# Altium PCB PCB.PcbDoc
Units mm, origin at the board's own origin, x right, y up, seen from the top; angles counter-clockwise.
Board outline 65.6 x 41.4 mm, 2 copper layers (Top Layer, Bottom Layer), stack 0.533 mm thick; 24 components, 81 nets, 201 pads, 130 vias.
Unrouted connection lines stored in the file: 11.
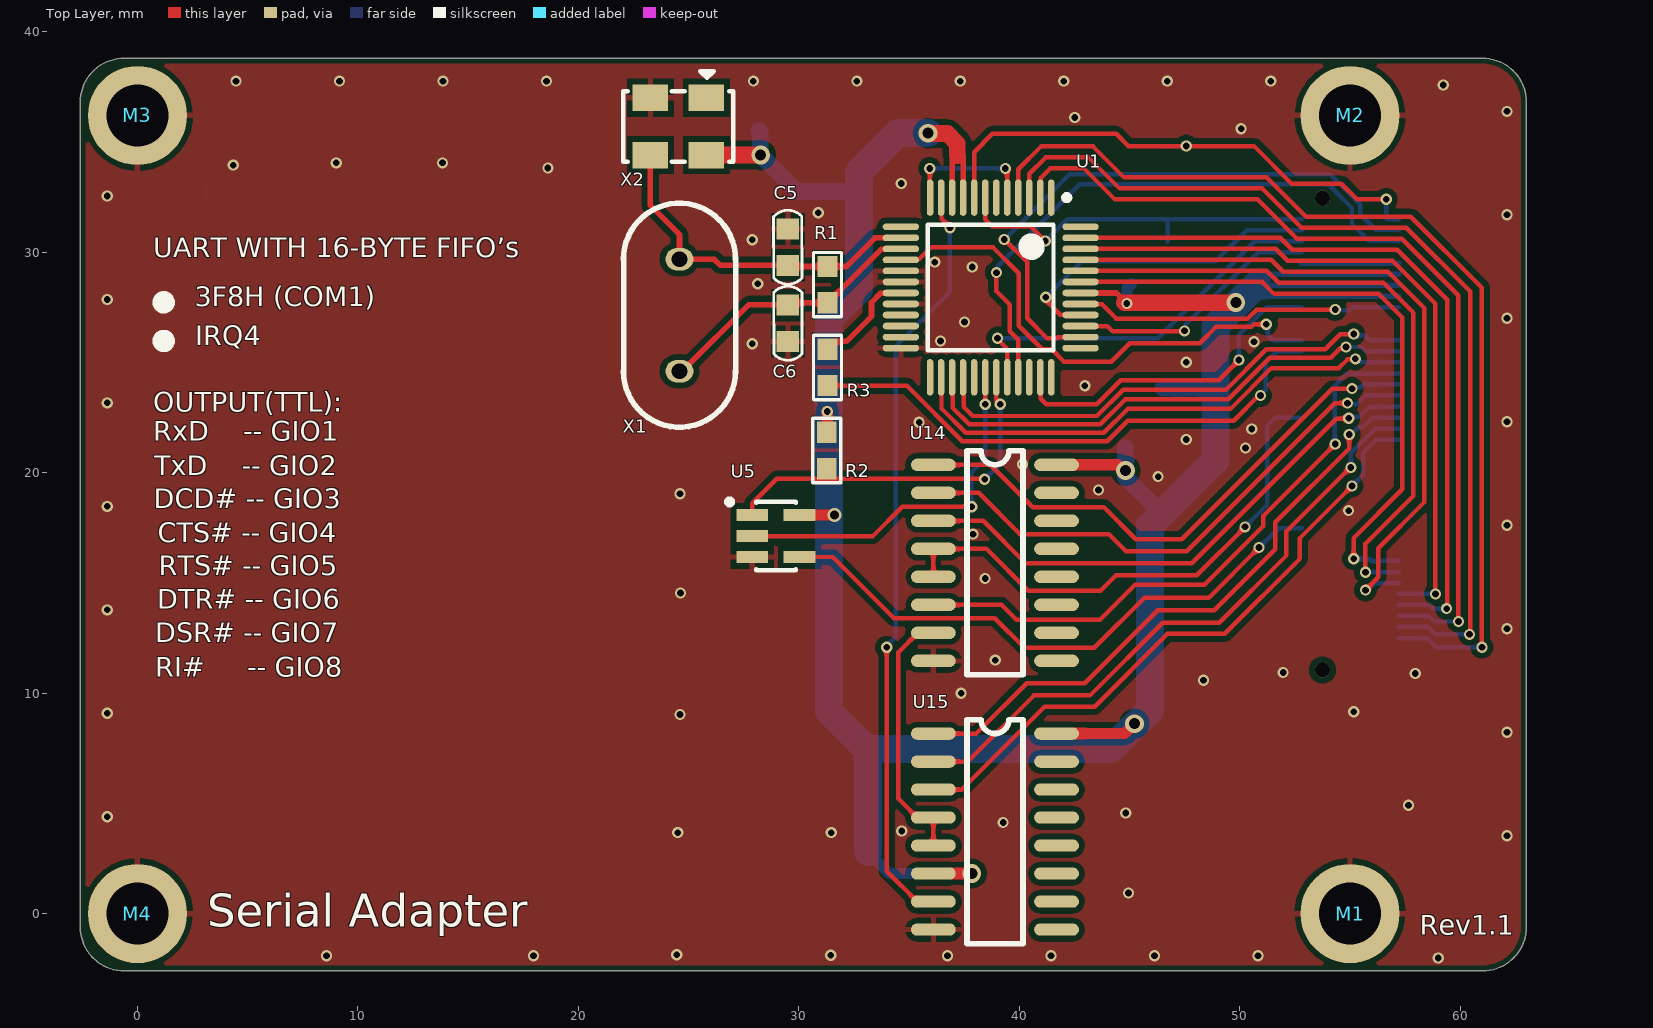
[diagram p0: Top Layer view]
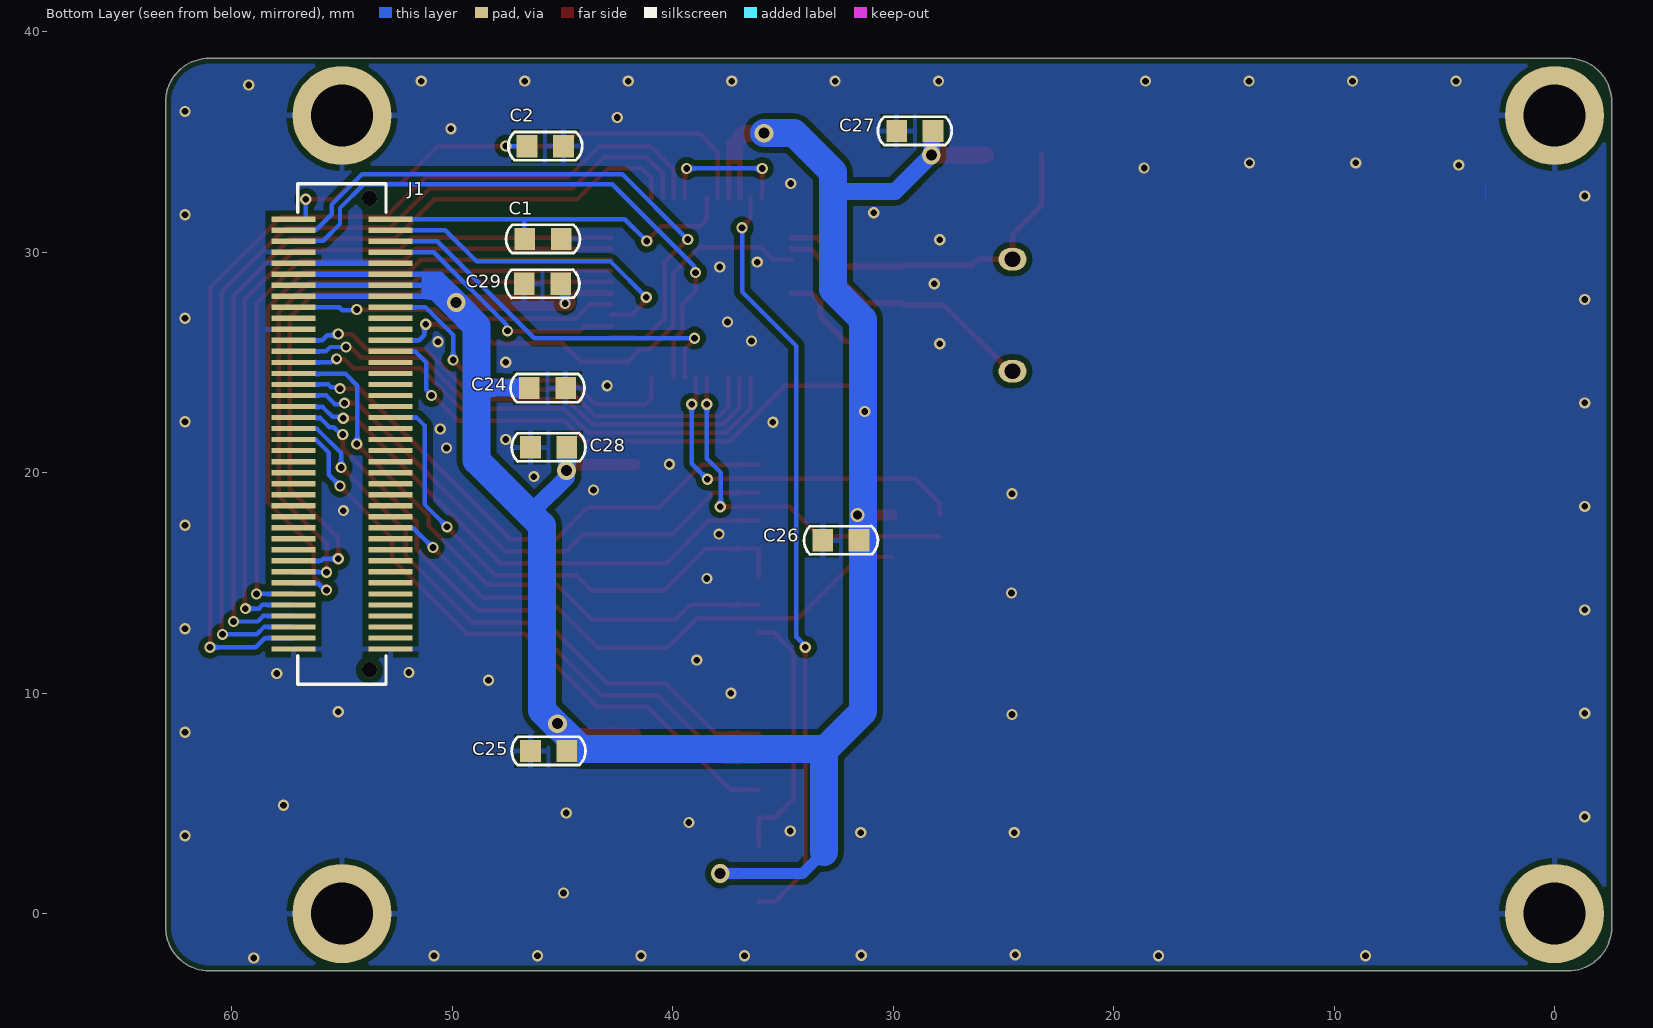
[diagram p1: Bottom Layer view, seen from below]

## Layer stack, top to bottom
Top Solder: solder mask 0.0102, Solder Resist, Dk 3.5
Top Layer: signal copper 0.0356
Dielectric 1: prepreg 0.0711, Composite dielectric, Dk 4.1
Dielectric1: prepreg 0.32, Composite dielectric, Dk 4.1
Dielectric 2: prepreg 0.0711, Composite dielectric, Dk 4.1
Bottom Layer: signal copper 0.0356
Bottom Solder: solder mask 0.0102, Solder Resist, Dk 3.5

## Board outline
-2.6,-0.6 ccw(c-0.6,-0.6) -0.6,-2.6 61,-2.6 ccw(c61,-0.6) 63,-0.6 63,36.803 63,36.8 ccw(c61,36.8) 61,38.8 -0.6,38.8 ccw(c-0.6,36.8) -2.6,36.8

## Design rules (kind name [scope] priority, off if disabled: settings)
BoardOutlineClearance [All] p1: gap=0 ignorepadtopadclearanceinfootprint=FALSE except(0.254: Poly-OutlineEdge Poly-CavityEdge Poly-CutoutEdge Poly-SplitBarrior)
Clearance [All] p1: gap=0.178 ignorepadtopadclearanceinfootprint=FALSE except(0.254: Arc-Fill Arc-Poly Arc-Region Track-Fill Track-Poly Track-Region SMDPad-Fill SMDPad-Poly SMDPad-Region THPad-Fill THPad-Poly THPad-Region Via-Fill Via-Poly Via-Region Fill-Fill Fill-Poly Fill-Region Poly-Poly Poly-Region Region-Region)
ComponentClearance [All] p1: gap=0 collisioncheckmode=3 verticalgap=0 showdistances=FALSE
Height [All] p1: minheight=0 maxheight=254 prefheight=12.7
HoleSize [All] p1: absolutevalues=TRUE maxlimit=254 minlimit=0.025 maxpercent=80.000 minpercent=20.000
MinimumSolderMaskSliver [All] p1: minsoldermaskwidth=0
PlaneClearance [All] p1: clearance=0.381
PlaneConnect PlaneConnect_1 [IsVia] p1: planeconnectstyle=Direct reliefexpansion=0.508 reliefentries=4 reliefconductorwidth=0.254 reliefairgap=0.254
PlaneConnect [All] p2: planeconnectstyle=Relief reliefexpansion=0.508 reliefentries=4 reliefconductorwidth=0.254 reliefairgap=0.254
PolygonConnect PolygonConnect_1 [IsVia] p1: connectstyle=Direct reliefconductorwidth=0.254 reliefentries=4 polygonreliefangle="90 Angle" airgapwidth=0.254
PolygonConnect [All] p2: connectstyle=Relief reliefconductorwidth=0.254 reliefentries=4 polygonreliefangle="90 Angle" airgapwidth=0.254
RoutingVias [All] p1: holewidth=0.305 width=0.559 viastyle="Through Hole" minholewidth=0.305 minwidth=0.508 maxholewidth=1.27 maxwidth=2.54
SilkToSilkClearance [All] p1: silktosilkclearance=0
SilkToSolderMaskClearance [IsPad] p1: minsilkscreentomaskgap=0 clearancetoexposedcopper=TRUE
SolderMaskExpansion [All] p1: expansion=0.102 istentingtop=FALSE useseparateexpansions=TRUE expansionbottom=0.102 istentingbottom=FALSE
UnRoutedNet [All] p1: checkbadconnections=TRUE
Width [All] p1: maxlimit=1.27 minlimit=0.203 preferedwidth=0.254 minimp=50.000000 maximp=50.000000 favimp=50.000000
21 further rules are at their usual default settings.

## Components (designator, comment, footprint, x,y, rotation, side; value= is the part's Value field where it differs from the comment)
C1 "47pf" C0603 45.055,30.596 r0 bottom
C2 "47pf" C0603 44.954,34.813 r0 bottom
C5 "20pf" C0603 29.5,31.051 r270 top
C6 "20pf" C0603 29.5,25.95 r90 top
C24 "10uf" C0603 46.503,23.84 r180 bottom
C25 "10uf" C0603 44.801,7.374 r0 bottom
C26 "0.1uf" C0603 31.543,16.931 r0 bottom
C27 "0.1uf" C0603 28.19,35.498 r0 bottom
C28 "0.1uf" C0603 44.801,21.147 r0 bottom
C29 "0.1uf" C0603 45.081,28.564 r0 bottom
J1 "CON40x2" BTB0.5-80P 53,12 r90 bottom locked
M1 "CON1" M2.5 55,0 r0 top locked
M2 "CON1" M2.5 55,36.2 r0 top locked
M3 "CON1" M2.5 0,36.2 r0 top locked
M4 "CON1" M2.5 0,0 r0 top locked
R1 "1M" R0603 31.3,27.7 r90 top
R2 "4.7k" R0603 31.263,21.833 r270 top
R3 "33" R0603 31.3,25.6 r270 top
U1 "ST16C550" LQFP48 38.7,28.4 r270 top
U5 "74LVC1G125" SOT23-5 27.885,18.074 r270 top
U14 "74LS138" SO-16 36.1,20.354 r0 top
U15 "74LS138" SO-16 36.1,8.164 r0 top
X1 "1.8432M" XTAL 24.583,27.142 r90 top
X2 "1.8432MM" CRY-5032 27.032,37.306 r180 top

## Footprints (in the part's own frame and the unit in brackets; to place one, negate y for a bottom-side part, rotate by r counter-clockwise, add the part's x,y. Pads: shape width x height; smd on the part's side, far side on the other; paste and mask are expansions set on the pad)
BTB0.5-80P [mm]
  rect 0.24x2 smd: 1(0,-0.2) 2(0,4.2) 3(0.5,-0.2) 4(0.5,4.2) 5(1,-0.2) 6(1,4.2) 7(1.5,-0.2) 8(1.5,4.2) 9(2,-0.2) 10(2,4.2) 11(2.5,-0.2) 12(2.5,4.2) 13(3,-0.2) 14(3,4.2) 15(3.5,-0.2) 16(3.5,4.2) 17(4,-0.2) 18(4,4.2) 19(4.5,-0.2) 20(4.5,4.2) 21(5,-0.2) 22(5,4.2) 23(5.5,-0.2) 24(5.5,4.2) 25(6,-0.2) 26(6,4.2) 27(6.5,-0.2) 28(6.5,4.2) 29(7,-0.2) 30(7,4.2) 31(7.5,-0.2) 32(7.5,4.2) 33(8,-0.2) 34(8,4.2) 35(8.5,-0.2) 36(8.5,4.2) 37(9,-0.2) 38(9,4.2) 39(9.5,-0.2) 40(9.5,4.2) 41(10,-0.2) 42(10,4.2) 43(10.5,-0.2) 44(10.5,4.2) 45(11,-0.2) 46(11,4.2) 47(11.5,-0.2) 48(11.5,4.2) 49(12,-0.2) 50(12,4.2) 51(12.5,-0.2) 52(12.5,4.2) 53(13,-0.2) 54(13,4.2) 55(13.5,-0.2) 56(13.5,4.2) 57(14,-0.2) 58(14,4.2) 59(14.5,-0.2) 60(14.5,4.2) 61(15,-0.2) 62(15,4.2) 63(15.5,-0.2) 64(15.5,4.2) 65(16,-0.2) 66(16,4.2) 67(16.5,-0.2) 68(16.5,4.2) 69(17,-0.2) 70(17,4.2) 71(17.5,-0.2) 72(17.5,4.2) 73(18,-0.2) 74(18,4.2) 75(18.5,-0.2) 76(18.5,4.2) 77(19,-0.2) 78(19,4.2) 79(19.5,-0.2) 80(19.5,4.2)
  silkscreen extent -1.6,0 21.1,4
C0603 [mil]
  rect 37.01x40 smd: 1(0,0)
  rect 37x40 smd: 2(65,0)
  silkscreen extent -34,-25 98,25
CRY-5032 [mm]
  rect 1.6x1.2 smd: 1(1.23,0.3) 2(3.77,0.3) 3(3.77,2.9) 4(1.23,2.9)
  silkscreen extent 0,-0.9 5,3.2
LQFP48 [mm] "LQFP, 48-Leads, Body 9.0x9.0mm (max), Pitch 0.50mm, IPC Medium Density"
  oval 1.65x0.3 smd: 1(-4.075,2.75) 2(-4.075,2.25) 3(-4.075,1.75) 4(-4.075,1.25) 5(-4.075,0.75) 6(-4.075,0.25) 7(-4.075,-0.25) 8(-4.075,-0.75) 9(-4.075,-1.25) 10(-4.075,-1.75) 11(-4.075,-2.25) 12(-4.075,-2.75) 25(4.075,-2.75) 26(4.075,-2.25) 27(4.075,-1.75) 28(4.075,-1.25) 29(4.075,-0.75) 30(4.075,-0.25) 31(4.075,0.25) 32(4.075,0.75) 33(4.075,1.25) 34(4.075,1.75) 35(4.075,2.25) 36(4.075,2.75)
  oval 0.3x1.65 smd: 13(-2.75,-4.075) 14(-2.25,-4.075) 15(-1.75,-4.075) 16(-1.25,-4.075) 17(-0.75,-4.075) 18(-0.25,-4.075) 19(0.25,-4.075) 20(0.75,-4.075) 21(1.25,-4.075) 22(1.75,-4.075) 23(2.25,-4.075) 24(2.75,-4.075) 37(2.75,4.075) 38(2.25,4.075) 39(1.75,4.075) 40(1.25,4.075) 41(0.75,4.075) 42(0.25,4.075) 43(-0.25,4.075) 44(-0.75,4.075) 45(-1.25,4.075) 46(-1.75,4.075) 47(-2.25,4.075) 48(-2.75,4.075)
  silkscreen extent -4.2,-2.85 2.85,3.58
M2.5 [mm]
  round 4.5 hole 2.8: 1(0,0)
R0603 [mil]
  rect 38x35 smd: 1(0,0) 2(65,0)
  silkscreen extent -25,-25 90,25
SO-16 [mil]
  oval 80x22 smd: 1(0,0) 2(0,-50) 3(0,-100) 4(0,-150) 5(0,-200) 6(0,-250) 7(0,-300) 8(0,-350) 9(220,-350) 10(220,-300) 11(220,-250) 12(220,-200) 13(220,-150) 14(220,-100) 15(220,-50) 16(220,0)
  silkscreen extent 60,-375 160,25
SOT23-5 [mm]
  rect 0.55x1.45 smd: 1(0,0) 2(0.95,0) 3(1.9,0) 4(1.9,2.15) 5(0,2.15)
  silkscreen extent -0.72,-1.15 2.5,1.98
XTAL [mil]
  oval 40x50 hole 28: 1(-100,0) 2(100,0)
  silkscreen extent -200,-100 200,100

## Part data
C1 C2 C5 C6 C24 C25 C26 C27 C28 C29: library part 0CAP
R1 R2 R3: library part 0RES
X1: library part CRYSTAL
X2: library part CRYSTAL-4P

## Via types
v1: diameter 0.508, hole 0.305, Top Layer to Bottom Layer, tented both sides, 121 vias
v2: diameter 0.85, hole 0.5, Top Layer to Bottom Layer, tented both sides, 6 vias
v3: diameter 0.7, hole 0.7, Top Layer to Bottom Layer, 2 vias
v4: diameter 0.635, hole 0.406, Top Layer to Bottom Layer, 1 vias

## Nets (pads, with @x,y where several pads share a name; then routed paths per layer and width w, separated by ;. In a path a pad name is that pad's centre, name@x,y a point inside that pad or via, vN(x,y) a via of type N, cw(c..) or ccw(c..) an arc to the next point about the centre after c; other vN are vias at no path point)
A0: J1.58 U1.28 | length 22.9
  Top Layer w0.203: U1.28 37.469,24.306 37.469,22.985 37.883,22.57 43.515,22.57 44.709,23.764 49.373,23.764 51.202,25.592 53.869,25.592 54.555,26.278 55.161,26.278 v1(55.17,26.287)
  Bottom Layer w0.203: v1(55.17,26.287) 55.228,26.229 55.666,26.229 55.895,26 J1.58
A1: J1.56 U1.27 | length 23.5
  Top Layer w0.203: U1.27 36.969,24.306 36.969,22.946 37.726,22.189 43.673,22.189 44.811,23.327 49.475,23.327 51.36,25.211 54.123,25.211 54.553,25.641 54.758,25.641 v1(54.817,25.7)
  Bottom Layer w0.203: v1(54.817,25.7) 55.527,25.7 55.727,25.5 J1.56
A2: J1.54 U1.26 | length 24.1
  Top Layer w0.203: U1.26 36.469,24.306 36.469,22.907 37.568,21.808 43.831,21.808 44.912,22.889 49.577,22.889 51.431,24.744 54.494,24.744 54.884,25.134 55.214,25.134 v1(55.241,25.161)
  Bottom Layer w0.203: v1(55.241,25.161) 55.323,25.161 55.484,25 J1.54
A3: J1.52 U14.6 | length 27.9
  Top Layer w0.203: U14.6 39.194,14.004 39.874,13.324 43.658,13.324 45.259,14.924 48.408,14.924 51.062,17.579 51.062,18.036 v1(54.326,21.3)
  Bottom Layer w0.203: v1(54.326,21.3) 54.301,21.325 54.301,23.941 54.841,24.482 57.182,24.482 J1.52
A4: J1.50 U14.1 | length 25.4
  Top Layer w0.203: U14.1 38.678,20.354 40.603,18.43 43.836,18.43 45.284,16.982 47.367,16.982 54.195,23.81 v1(55.085,23.81)
  Bottom Layer w0.203: v1(55.085,23.81) 55.143,23.868 55.49,23.868 55.622,24 J1.50
A5: J1.48 U14.2 | length 25.2
  Top Layer w0.203: U14.2 38.152,19.084 40.026,17.21 44.065,17.21 44.839,16.436 47.593,16.436 54.311,23.154 v1(54.885,23.154)
  Bottom Layer w0.203: v1(54.885,23.154) 54.935,23.105 55.318,23.105 55.714,23.5 J1.48
A6: J1.46 U14.3 | length 24.8
  Top Layer w0.203: U14.3 38.355,17.814 40.28,15.89 47.819,15.89 54.381,22.451 54.921,22.451 v1(54.94,22.47)
  Bottom Layer w0.203: v1(54.94,22.47) 54.998,22.529 55.426,22.529 55.879,22.982 57.182,22.982 J1.46
A7: J1.44 U15.1 | length 28.1
  Top Layer w0.203: U15.1 38.041,8.164 40.331,10.454 42.973,10.454 46.275,13.756 48.84,13.756 51.609,16.525 51.609,17.744 54.961,21.097 v1(54.961,21.732)
  Bottom Layer w0.203: v1(54.961,21.732) 55.044,21.732 55.371,22.059 55.568,22.059 55.991,22.482 57.182,22.482 J1.44
A8: J1.42 U15.2 | length 28.4
  Top Layer w0.203: U15.2 37.66,6.894 40.661,9.895 43.204,9.895 46.506,13.197 49.069,13.197 52.117,16.245 52.117,17.337 55.012,20.233 v1(55.038,20.233)
  Bottom Layer w0.203: v1(55.038,20.233) 55.038,20.892 56.128,21.982 57.182,21.982 J1.42
A9: J1.40 U15.3 | length 28.8
  Top Layer w0.203: U15.3 37.38,5.624 41.144,9.387 43.414,9.387 46.716,12.689 49.323,12.689 52.726,16.093 52.726,17.033 v1(55.088,19.395)
  Bottom Layer w0.203: v1(55.088,19.395) 55.596,19.903 55.596,20.912 56.166,21.482 57.182,21.482 J1.40
A10: J1.38
A11: J1.36
A12: J1.34
A13: J1.32
A14: J1.30
A15: J1.28
A16: J1.26
A17: J1.24
A18: J1.22
A19: J1.20
AEN: J1.43 U14.4 U14.5 | length 24.1
  Top Layer w0.203: U14.5 U14.4 38.508,16.544 40.407,14.645 43.684,14.645 44.382,15.344 48.045,15.344 v1@50.24,17.538
  Bottom Layer w0.203: v1(50.237,17.541) 51.253,18.557 51.253,22.138 51.615,22.5 J1.43
ALE: J1.49
BHE#: J1.41
COM1CS#: U1.11 U15.7 | length 34.6
  Top Layer w0.203: v1(33.981,12.08) 33.981,1.926 35.363,0.544 U15.7 ; U1.11 36.469,32.456 36.469,31.512 36.851,31.129 v1(36.851,31.104)
  Bottom Layer w0.203: v1(33.981,12.08) 33.981,12.148 34.387,12.554 34.387,25.745 36.851,28.209 v1(36.851,31.104)
CTS#: J1.78 U1.38 | length 27.3
  Top Layer w0.203: v1(39.315,30.571) 39.34,30.571 40.356,29.555 40.356,26.997 41.253,26.1 41.695,26.1 41.745,26.15 U1.38
  Bottom Layer w0.203: v1(39.315,30.571) 42.287,33.543 54.086,33.543 55.47,32.159 55.47,31.715 56.166,31.018 57.182,31.018 J1.78
D0: J1.18 U1.43 | length 29.2
  Top Layer w0.203: U1.43 51.011,28.65 51.554,28.107 56.307,28.107 57.374,27.04 57.374,19.242 55.165,17.033 v1(55.165,16.093)
  Bottom Layer w0.203: v1(55.165,16.093) 55.843,16.093 55.936,16 J1.18
D1: J1.16 U1.44 | length 30.1
  Top Layer w0.203: U1.44 51.218,29.15 51.761,28.607 56.515,28.607 57.874,27.247 57.874,18.955 55.698,16.779 v1(55.698,15.483)
  Bottom Layer w0.203: v1(55.698,15.483) 55.706,15.492 57.192,15.492 J1.16
D2: J1.14 U1.45 | length 32
  Top Layer w0.203: U1.45 51.425,29.65 51.968,29.107 56.722,29.107 58.374,27.454 58.374,18.668 56.282,16.575 56.282,15.255 v1(55.698,14.67)
  Bottom Layer w0.203: v1(55.698,14.67) 55.78,14.67 56.092,14.982 57.182,14.982 J1.14
D3: J1.12 U1.46 | length 32
  Top Layer w0.203: U1.46 51.632,30.15 52.175,29.607 56.929,29.607 58.874,27.662 58.874,14.494 v1(58.873,14.493)
  Bottom Layer w0.203: J1.12 57.204,14.496 58.869,14.496 v1(58.873,14.493)
D4: J1.10 U1.47 | length 34.1
  Top Layer w0.203: U1.47 51.839,30.65 52.382,30.107 57.136,30.107 59.406,27.837 59.406,13.858 v1(59.381,13.832)
  Bottom Layer w0.203: J1.10 58.611,14 58.779,13.832 v1(59.381,13.832)
D5: J1.8 U1.2 | length 40
  Top Layer w0.203: U1.2 40.969,32.494 40.969,33.367 41.398,33.797 42.93,33.797 44.336,32.39 50.813,32.39 52.591,30.612 57.345,30.612 59.914,28.043 v1(59.914,13.248)
  Bottom Layer w0.203: J1.8 58.572,13.5 58.824,13.248 v1(59.914,13.248)
D6: J1.6 U1.3 | length 42.8
  Top Layer w0.203: U1.3 40.45,33.556 41.191,34.297 43.137,34.297 44.543,32.89 51.02,32.89 52.798,31.112 57.552,31.112 60.448,28.217 60.448,12.689 v1(60.422,12.664)
  Bottom Layer w0.203: J1.6 58.534,13 58.87,12.664 v1(60.422,12.664)
D7: J1.4 U1.4 | length 45.7
  Top Layer w0.203: U1.4 39.95,33.763 40.984,34.797 43.344,34.797 44.751,33.39 51.228,33.39 53.006,31.612 57.759,31.612 60.981,28.39 v1(60.981,12.08)
  Bottom Layer w0.203: J1.4 57.21,12.49 58.505,12.49 58.915,12.08 v1(60.981,12.08)
D8: J1.17
D9: J1.15
D10: J1.13
D11: J1.11
D12: J1.9
D13: J1.7
D14: J1.5
D15: J1.3
DCD#: J1.77 U1.40 | length 14.9
  Top Layer w0.203: v1(41.195,27.955) 41.253,27.896 41.253,27.769 41.854,27.169 42.756,27.169 U1.40
  Bottom Layer w0.203: v1(41.195,27.955) 42.82,29.58 48.891,29.58 50.311,31 J1.77
DSR#: J1.73 U1.39 | length 11.7
  Top Layer w0.203: U1.39 43.992,26.65 44.236,26.405 47.468,26.405 v1(47.494,26.431)
  Bottom Layer w0.203: v1(47.494,26.431) 47.552,26.489 47.552,26.718 50.835,30 J1.73
DTR#: J1.76 U1.33 | length 26.7
  Top Layer w0.203: v1(38.959,29.072) 38.959,28.234 39.569,27.624 39.569,26.411 39.95,26.03 U1.33
  Bottom Layer w0.203: v1(38.959,29.072) 39.018,29.131 39.018,29.359 42.738,33.079 54.011,33.079 55.089,32.002 55.089,31.282 55.852,30.518 57.182,30.518 J1.76
GIO9: J1.62
GND: C1.1 C2.1 C5.1 C6.1 C24.2 C25.2 C26.2 C27.2 C28.2 C29.2 J1.1 J1.2 J1.60 J1.71 J1.72 J1.74 M1.1 M2.1 M3.1 M4.1 U1.17 U1.18 U1.20 U1.24 U5.3 U14.8 U15.8 X2.2 | length 4.4
  Bottom Layer w0.254: J1.71 J1.72
  other v1: 59,-2.017 8.576,-1.916 17.964,-1.916 36.739,-1.916 41.433,-1.916 46.127,-1.916 50.821,-1.916 31.441,-1.89 24.456,-1.865 44.954,0.929 62.124,3.53 24.507,3.672 31.466,3.672 34.663,3.742 39.264,4.129 -1.376,4.388 44.827,4.561 57.654,4.917 62.124,8.224 24.608,9.032 -1.376,9.082 55.165,9.159 37.359,9.997 48.357,10.581 57.959,10.886 51.964,10.937 38.909,11.495 62.124,12.918 -1.376,13.776 24.63,14.537 38.447,15.197 37.893,17.21 62.124,17.612 54.936,18.277 -1.376,18.47 24.608,19.039 43.594,19.21 46.296,19.82 40.149,20.379 50.258,21.115 47.57,21.503 50.538,21.979 35.454,22.29 62.124,22.306 -1.376,23.164 42.973,23.941 47.57,25.008 27.885,25.846 50.639,25.941 36.419,25.973 37.512,26.837 62.124,27 -1.376,27.858 28.134,28.567 37.867,29.326 36.161,29.548 27.881,30.564 62.124,31.693 30.882,31.79 -1.376,32.552 34.641,33.111 18.614,33.822 4.339,33.949 9.013,34.051 13.839,34.051 50.059,35.6 42.515,36.108 62.124,36.387 59.229,37.581 4.466,37.759 9.16,37.759 13.854,37.759 18.548,37.759 27.936,37.759 32.63,37.759 37.324,37.759 42.018,37.759 46.711,37.759 51.405,37.759
IOCS16#: J1.33
IOR#: J1.55 R3.2 | length 25
  Top Layer w0.203: R3.2 34.888,23.949 37.41,21.427 43.989,21.427 44.918,22.356 49.718,22.356 50.858,23.495 v1(50.937,23.495)
  Bottom Layer w0.203: v1(50.937,23.495) 50.937,23.527 51.177,23.767 51.177,24.992 51.685,25.5 J1.55
IORDY: J1.45
IOW#: J1.57 U1.16 | length 23.2
  Top Layer w0.203: U1.16 34.644,29.669 35.441,29.669 35.988,30.215 38.807,30.215 39.975,29.047 39.975,26.659 41.042,25.592 41.465,25.592 42.024,25.034 44.166,25.034 45.005,25.872 48.18,25.872 48.916,26.608 50.522,26.608 50.643,26.73 51.197,26.73 v1(51.202,26.735)
  Bottom Layer w0.203: v1(51.202,26.735) 51.261,26.677 51.261,26.235 51.495,26 J1.57
IRQ3: J1.21
IRQ4: J1.23 U5.4 | length 26.7
  Top Layer w0.203: U5.4 31.538,16.174 34.311,13.4 38.883,13.4 40.229,12.054 43.404,12.054 45.665,14.315 48.586,14.315 v1(50.872,16.601)
  Bottom Layer w0.203: v1(50.872,16.601) 50.886,16.601 51.766,17.482 52.782,17.482 J1.23
IRQ5: J1.25
IRQ9: J1.19
IRQ10: J1.27
IRQ11: J1.29
IRQ15: J1.31
MCS16#: J1.35
MEMR#: J1.39
MEMW#: J1.37
NetR3_1: R3.1 U1.19 | length 4.8
  Top Layer w0.254: R3.1 31.3,25.638 31.618,25.956 32.16,25.956 33.295,27.091 33.295,27.726 33.713,28.144 34.619,28.144 U1.19
NetU1_30: U1.30 U5.2 | length 16.7
  Top Layer w0.203: U5.2 33.361,17.124 34.692,18.455 v1(37.842,18.455) ; v1(38.449,23.103) U1.30
  Bottom Layer w0.203: v1(37.842,18.455) 37.816,18.48 37.816,20.004 38.451,20.639 38.451,23.101 v1(38.449,23.103)
NetU14_7: U14.7 U15.4 U15.5 | length 11.8
  Top Layer w0.203: U15.5 U15.4 35.363,4.354 34.514,5.203 34.514,11.851 35.398,12.734 U14.7
OSC: J1.47
OUT1#: U1.34
OUT2#: R2.2 U1.31 U5.1 | length 16.5
  Top Layer w0.203: U5.1 27.885,18.607 29.003,19.725 38.401,19.725 v1(38.426,19.7) ; U1.31 38.95,23.289 v1(39.135,23.103)
  Bottom Layer w0.203: v1(38.426,19.7) 39.135,20.409 v1(39.135,23.103)
RCLK: U1.5 U1.12 | length 6.1
  Top Layer w0.203: v1(35.937,33.797) 35.943,33.79 35.943,32.482 U1.12 ; v1(39.366,33.797) 39.366,33.714 39.45,33.63 U1.5
  Bottom Layer w0.203: v1(35.937,33.797) v1(39.366,33.797)
REFSH#: J1.53
RESET: J1.63 U1.35 | length 15.4
  Top Layer w0.203: U1.35 40.969,24.306 40.969,23.355 41.22,23.103 43.504,23.103 44.597,24.195 49.051,24.195 49.958,25.102 v1(49.958,25.11)
  Bottom Layer w0.203: v1(49.958,25.11) 49.958,26.245 51.212,27.5 J1.63
RI#: J1.64 U1.41 | length 14.9
  Top Layer w0.203: U1.41 42.794,27.631 43.753,27.631 44.395,26.989 50.364,26.989 50.77,27.396 v1(54.326,27.396)
  Bottom Layer w0.203: v1(54.326,27.396) 54.358,27.364 54.987,27.364 55.123,27.5 J1.64
RTS#: J1.75 U1.32 | length 17.6
  Top Layer w0.203: v1(39.01,26.1) 39.01,26.046 39.45,25.606 U1.32
  Bottom Layer w0.203: v1(39.01,26.1) 46.275,26.1 50.674,30.5 J1.75
RxD: C1.2 J1.79 U1.7 | length 17.2
  Top Layer w0.203: U1.7 38.45,31.487 38.756,31.18 40.509,31.18 v1(41.178,30.511)
  Bottom Layer w0.203: v1(41.178,30.511) 42.167,31.5 46.732,31.5 ; C1.2@46.732,30.469 46.732,31.5 ; J1.79 46.732,31.5
RXRDY#: U1.29
SMEMR#: J1.59
SMEMW#: J1.61
SYSCLK: J1.51
TxD: C2.2 J1.80 U1.8 | length 24.7
  Top Layer w0.203: U1.8@37.947,32.472 U1.8 37.95,34.54 38.775,35.365 44.392,35.365 44.944,34.812 v1(47.57,34.813) 50.643,34.813 52.345,33.111 54.606,33.111 55.317,32.4 v1(56.638,32.4)
  Bottom Layer w0.203: C2.2 v1(47.57,34.813) ; v1(56.638,32.4) 56.638,31.518 56.656,31.5 J1.80
TXRDY#: U1.23
VCC: C24.1 C25.1 C26.1 C27.1 C28.1 C29.1 J1.65 J1.66 J1.67 J1.68 J1.69 J1.70 R2.1 U1.9 U1.10 U1.42 U5.5 U14.16 U15.6 U15.16 X2.4 | length 136.4
  Top Layer w0.254: U1.10 36.95,34.381 ; U1.9 37.45,34.381 ; U1.42 44.403,28.15 v1@44.776,27.777
  Top Layer w0.508: U5.5 v4(31.619,18.074) ; R2.1@31.098,21.782 R2.1@31.289,21.973 ; R2.1 31.289,21.859 R2.1@31.289,21.973 ; v1(31.289,22.773) R2.1@31.289,21.973 ; U15.6 36.102,1.816 37.84,1.816 v2(37.842,1.818) ; U15.16 44.772,8.164 v2@45.055,8.447 ; U14.16 44.46,20.354 44.722,20.093 v2(44.814,20.093)
  Top Layer w0.762: X2.4 v2(28.266,34.406) ; v2(35.861,35.397) 35.877,35.38 36.735,35.38 37.181,34.934 37.181,34.381 ; v1@44.77,27.707 49.811,27.707 v2(49.818,27.713) v2@49.831,27.726
  Bottom Layer w0.254: J1.66 J1.65 50.266,28 49.979,27.713 v2(49.818,27.713) 50.605,28.5 ; J1.68 J1.67 50.605,28.5 ; J1.70 J1.69 51.105,29 50.605,28.5
  Bottom Layer w0.508: 33.143,2.783 34.108,1.818 v2(37.842,1.818) ; v1(44.878,27.675) 44.878,28.361 C29.1
  Bottom Layer w0.762: C27.1 28.249,35.439 28.249,34.423 v2(28.266,34.406) 29.917,32.755 32.736,32.755 ; v2@44.801,19.801 46.262,18.341 46.668,18.341 ; v2@44.801,20.093 C28.1 ; C24.1 48.889,23.84
  Bottom Layer w1.27: 33.067,7.457 31.365,9.159 31.365,26.939 32.736,28.31 32.736,32.755 32.736,33.644 34.489,35.397 v2(35.861,35.397) ; 33.143,2.783 33.143,7.33 ; 33.143,7.457 44.166,7.457 ; 44.256,7.547 45.919,9.209 45.919,17.591 46.668,18.341 48.889,20.562 48.889,23.84 48.889,26.658 v2@49.878,27.646
  other v2: 45.22,8.613
X1: C5.2 R1.2 U1.14 X1.2 X2.3 | length 16
  Top Layer w0.254: X2.3 23.262,32.12 24.583,30.799 X1.2 26.158,29.682 26.44,29.4 C5.2 29.549,29.351 R1.2 32.151,29.351 33.45,30.65 U1.14
X2: C6.2 R1.1 U1.15 X1.1 | length 12.2
  Top Layer w0.254: X1.1 24.71,24.602 27.733,27.624 C6.2@29.333,27.624 ; C6.2 29.6,27.7 R1.1 31.3,27.738 31.618,28.056 31.656,28.056 33.741,30.141 34.616,30.141 U1.15
pads on no net: U1.1 U1.6 U1.13 U1.21 U1.22 U1.25 U1.36 U1.37 U1.48 U14.9 U14.10 U14.11 U14.12 U14.13 U14.14 U14.15 U15.9 U15.10 U15.11 U15.12 U15.13 U15.14 U15.15 X2.1
copper on no net:
  other v3: 53.75,11.05 53.75,32.45

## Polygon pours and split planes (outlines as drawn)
GND on Bottom Layer "NONET_L-01_P-001" (solid, remove dead copper, pour order 0): -2.702,-0.6 -2.702,36.8 cw(c-0.6,36.8) -0.6,38.902 61.003,38.902 cw(c61,36.8) 63.102,36.803 63.102,-0.6 cw(c61,-0.6) 61,-2.702 -0.6,-2.702 cw(c-0.6,-0.6)
GND on Top Layer "NONET_L-01_P-001" (solid, remove dead copper, pour order 1): -2.702,-0.6 -2.702,36.8 cw(c-0.6,36.8) -0.6,38.902 61.003,38.902 cw(c61,36.8) 63.102,36.803 63.102,-0.6 cw(c61,-0.6) 61,-2.702 -0.6,-2.702 cw(c-0.6,-0.6)

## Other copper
Bottom Layer:
  region net VCC: 51.381,29.123 50.466,29.123 49.272,27.929 49.272,26.939 49.297,26.939 49.348,26.888 49.678,27.218 50.313,27.218 50.923,27.828 51.381,27.878

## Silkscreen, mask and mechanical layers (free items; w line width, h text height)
Top Overlay:
  circle w0.508: c1.19,25.973 r0.254
  circle w0.508: c1.19,27.726 r0.254
  text "UART WITH 16-BYTE FIFO’s" at 0.707,29.479 h1.52
  text "3F8H (COM1)" at 2.587,27.252 h1.52
  text "IRQ4" at 2.612,25.491 h1.52
  text "OUTPUT(TTL):" at 0.707,22.468 h1.52
  text "RxD    -- GIO1" at 0.707,21.147 h1.52
  text "TxD    -- GIO2" at 0.758,19.598 h1.52
  text "DCD# -- GIO3" at 0.732,18.099 h1.52
  text "CTS# -- GIO4" at 0.91,16.55 h1.52
  text "RTS# -- GIO5" at 0.961,15.051 h1.52
  text "DTR# -- GIO6" at 0.885,13.527 h1.52
  text "DSR# -- GIO7" at 0.809,12.003 h1.52
  text "RI#     -- GIO8" at 0.809,10.454 h1.52
  text "Serial Adapter" at 3.171,-1.103 h2.54
  text "Rev1.1" at 58.162,-1.255 h1.52
Mechanical 1:
  lines w0.127: -2.6,-0.6 ccw(c-0.6,-0.6) -0.6,-2.6 61,-2.6 ccw(c61,-0.6) 63,-0.6 63,36.803 63,36.8 ccw(c61,36.8) 61,38.8 -0.6,38.8 ccw(c-0.6,36.8) -2.6,36.8 -2.6,-0.6
  lines w0.203: 61,38.8 cw(c61,36.8) 63,36.8 ; 61.003,38.8 -0.6,38.8 ccw(c-0.6,36.8) -2.6,36.8 -2.6,-0.6 ccw(c-0.6,-0.6) -0.6,-2.6 61,-2.6 ccw(c61,-0.6) 63,-0.6 63,36.803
